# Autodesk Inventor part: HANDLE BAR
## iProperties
Created: 2006-07
Part Number: HANDLE BAR
Material: Steel
Document SubType Name: Modeling
Designer: rollin42
Mass: 53.2788 g
Surface Area: 29.9274 cm^2
Volume: 6.78711 cm^3
Density: 7.85 g/cm^3
Author: rollin42
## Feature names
1. Extrusion1
